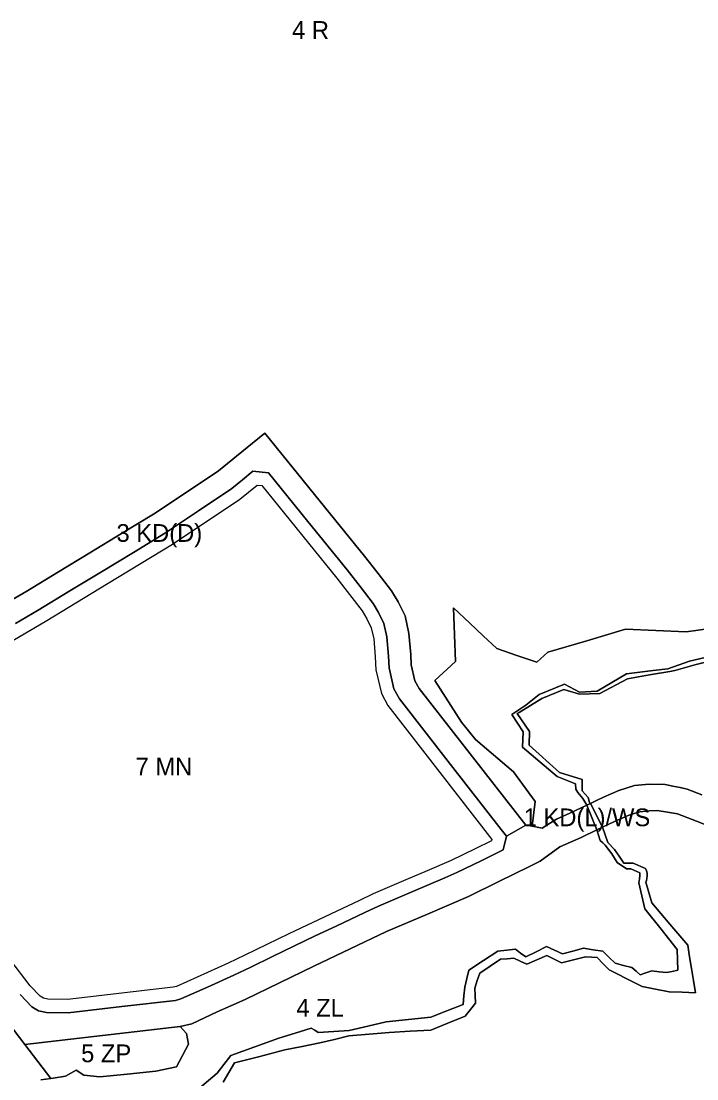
# Model space of a CAD drawing. Extents: x 7423691 to 7425475, y 5552085 to 5554331.
# Drawn here: x 7424684.6 to 7424989.2, y 5552921.5 to 5553398.6 of the extents above; entities that cross this region are included whole.
import ezdxf

# ---------------------------------------------------------------- set-up
doc = ezdxf.new("R2010")
doc.units = 0
for name, color, linetype in [('linia_zabudowy_nieprzekraczalna', 7, 'Continuous'), ('linie_rozgraniczajace', 7, 'Continuous'), ('oznaczenia_przeznaczen', 7, 'Continuous')]:
    doc.layers.add(name, color=color, linetype=linetype)

msp = doc.modelspace()

# ---------------------------------------------------------------- linework, layer by layer
at = {"layer": 'linia_zabudowy_nieprzekraczalna'}
for points in [[(7424674.46, 5553115.63), (7424695.37, 5553127.73), (7424723.87, 5553145.12), (7424752.83, 5553162.67), (7424783.11, 5553182.94), (7424790.96, 5553189.33), (7424793.03, 5553189.11), (7424826.84, 5553147.4), (7424838.36, 5553132.54), (7424840.47, 5553129.02), (7424842.45, 5553124.97), (7424843.56, 5553119.97), (7424844.25, 5553111.83), (7424844.49, 5553106.05), (7424847.02, 5553095.29), (7424849.93, 5553089.96), (7424896.85, 5553029.48)], [(7424896.85, 5553029.48), (7424896.71, 5553028.9), (7424889.27, 5553025.25), (7424878.52, 5553019.99), (7424867.66, 5553015.33), (7424858, 5553011.19), (7424843.26, 5553004.87), (7424837.06, 5553001.98), (7424823.99, 5552995.79), (7424805.25, 5552986.87), (7424785.48, 5552977.28), (7424777.98, 5552973.64), (7424754.64, 5552963.18), (7424753.04, 5552962.78), (7424705.5, 5552957.33), (7424696.62, 5552957.36), (7424694.72, 5552957.8), (7424693.22, 5552958.72), (7424688.62, 5552963.41), (7424642.68, 5553023.53)]]:
    msp.add_lwpolyline(points, dxfattribs=at)
at = {"layer": 'linie_rozgraniczajace'}
for points in [[(7424996.23, 5553124.78), (7424984.37, 5553123.2), (7424970.73, 5553123.77), (7424957.08, 5553124.35), (7424939.57, 5553119.13), (7424922.06, 5553113.91), (7424917.04, 5553109.37), (7424908.04, 5553112.51), (7424899.05, 5553115.64), (7424892.95, 5553121.31), (7424886.85, 5553126.98), (7424879.56, 5553133.99), (7424879.99, 5553121.83), (7424880.42, 5553109.68), (7424871.08, 5553101.21), (7424883.09, 5553082.35), (7424889.46, 5553074.63), (7424906.56, 5553060.01), (7424916.29, 5553046.64), (7424914.96, 5553035.43), (7424912.13, 5553035.95), (7424888.05, 5553066.79), (7424863.97, 5553097.63), (7424862.1, 5553101.06), (7424860.41, 5553108.23), (7424860.23, 5553112.84), (7424859.41, 5553122.39), (7424857.66, 5553130.28), (7424854.55, 5553136.66), (7424851.59, 5553141.58), (7424845.49, 5553149.46), (7424839.38, 5553157.34), (7424816.9, 5553185.06), (7424794.43, 5553212.79), (7424784.01, 5553204.3), (7424773.59, 5553195.81), (7424758.91, 5553185.99), (7424744.23, 5553176.17), (7424729.89, 5553167.48), (7424715.55, 5553158.79), (7424701.38, 5553150.14), (7424687.2, 5553141.48), (7424677.14, 5553135.66)], [(7424677.14, 5553135.66), (7424687.2, 5553141.48), (7424701.38, 5553150.14), (7424715.55, 5553158.79), (7424729.89, 5553167.48), (7424744.23, 5553176.17), (7424758.91, 5553185.99), (7424773.59, 5553195.81), (7424784.01, 5553204.3), (7424794.43, 5553212.79), (7424816.9, 5553185.06), (7424839.38, 5553157.34), (7424845.49, 5553149.46), (7424851.59, 5553141.58), (7424854.55, 5553136.66), (7424857.66, 5553130.28), (7424859.41, 5553122.39), (7424860.23, 5553112.84), (7424860.41, 5553108.23), (7424862.1, 5553101.06), (7424863.97, 5553097.63), (7424888.05, 5553066.79), (7424912.13, 5553035.95), (7424903.34, 5553030.91), (7424900.95, 5553033.99), (7424878.13, 5553063.34), (7424855.2, 5553092.84), (7424852.68, 5553097.46), (7424850.46, 5553106.86), (7424850.24, 5553112.21), (7424849.51, 5553120.85), (7424848.16, 5553126.96), (7424845.75, 5553131.89), (7424843.33, 5553135.93), (7424837.44, 5553143.53), (7424831.55, 5553151.12), (7424813.83, 5553172.97), (7424796.12, 5553194.82), (7424789.1, 5553195.55), (7424784.32, 5553191.66), (7424779.54, 5553187.77), (7424764.57, 5553177.75), (7424749.6, 5553167.73), (7424735.18, 5553158.99), (7424720.75, 5553150.25), (7424706.53, 5553141.57), (7424692.31, 5553132.89), (7424682, 5553126.92)], [(7424682, 5553126.92), (7424692.31, 5553132.89), (7424706.53, 5553141.57), (7424720.75, 5553150.25), (7424735.18, 5553158.99), (7424749.6, 5553167.73), (7424764.57, 5553177.75), (7424779.54, 5553187.77), (7424784.32, 5553191.66), (7424789.1, 5553195.55), (7424796.12, 5553194.82), (7424813.83, 5553172.97), (7424831.55, 5553151.12), (7424837.44, 5553143.53), (7424843.33, 5553135.93), (7424845.75, 5553131.89), (7424848.16, 5553126.96), (7424849.51, 5553120.85), (7424850.24, 5553112.21), (7424850.46, 5553106.86), (7424852.68, 5553097.46), (7424855.2, 5553092.84), (7424878.13, 5553063.34), (7424900.95, 5553033.99), (7424903.34, 5553030.91), (7424901.92, 5553024.77), (7424891.91, 5553019.86), (7424881.02, 5553014.54), (7424875.53, 5553012.18), (7424860.36, 5553005.68), (7424845.71, 5552999.39), (7424839.6, 5552996.55), (7424826.56, 5552990.37), (7424817.21, 5552985.92), (7424807.85, 5552981.46), (7424797.97, 5552976.67), (7424788.1, 5552971.89), (7424780.51, 5552968.21), (7424768.56, 5552962.85), (7424756.61, 5552957.49), (7424754.12, 5552956.86), (7424729.97, 5552954.09), (7424705.83, 5552951.32), (7424695.93, 5552951.37), (7424692.42, 5552952.17), (7424689.45, 5552954), (7424684.08, 5552959.48)], [(7424871.08, 5553101.21), (7424880.42, 5553109.68), (7424879.99, 5553121.83), (7424879.56, 5553133.99), (7424886.85, 5553126.98), (7424892.95, 5553121.31), (7424899.05, 5553115.64), (7424908.04, 5553112.51), (7424917.04, 5553109.37), (7424922.06, 5553113.91), (7424939.57, 5553119.13), (7424957.08, 5553124.35), (7424970.73, 5553123.77), (7424984.37, 5553123.2), (7424996.23, 5553124.78)], [(7424905.79, 5553085.9), (7424912.07, 5553090.07), (7424915.07, 5553092.48), (7424918.07, 5553094.9), (7424929.53, 5553099.54), (7424936.36, 5553095.91), (7424944.3, 5553096.38), (7424957.55, 5553104.18), (7424969.52, 5553105.66), (7424976.1, 5553106.47), (7424985.93, 5553109.97), (7425000.71, 5553113.41)], [(7425000.71, 5553113.41), (7424985.93, 5553109.97), (7424976.1, 5553106.47), (7424969.52, 5553105.66), (7424957.55, 5553104.18), (7424944.3, 5553096.38), (7424936.36, 5553095.91), (7424929.53, 5553099.54), (7424918.07, 5553094.9), (7424915.07, 5553092.48), (7424912.07, 5553090.07)], [(7425000.54, 5553111.18), (7424988.39, 5553108.24), (7424984.16, 5553107.01), (7424979.93, 5553105.78), (7424977.91, 5553105.34), (7424967.93, 5553103.67), (7424957.95, 5553102), (7424945.48, 5553095.32), (7424936.31, 5553095.08), (7424929.21, 5553097.1), (7424919.4, 5553093.02), (7424914.25, 5553089.91), (7424909.1, 5553086.8), (7424908.18, 5553086.25), (7424913.8, 5553078.22), (7424913.62, 5553072.01), (7424927.23, 5553059.64), (7424937.53, 5553056.58), (7424937.55, 5553051.42), (7424940.22, 5553048.35), (7424940.79, 5553046.21), (7424941.28, 5553045.73), (7424939.69, 5553044.97), (7424937.82, 5553047.93), (7424935.58, 5553050.63), (7424934.74, 5553052.11), (7424934.59, 5553054.53), (7424926.29, 5553057.86), (7424918.48, 5553064.47), (7424910.67, 5553071.08), (7424910.91, 5553077.95), (7424905.79, 5553085.9)], [(7424908.18, 5553086.25), (7424909.1, 5553086.8), (7424914.25, 5553089.91), (7424919.4, 5553093.02), (7424929.21, 5553097.1), (7424936.31, 5553095.08), (7424945.48, 5553095.32), (7424957.95, 5553102), (7424967.93, 5553103.67), (7424977.91, 5553105.34), (7424979.93, 5553105.78), (7424984.16, 5553107.01), (7424988.39, 5553108.24), (7425000.54, 5553111.18)], [(7424912.07, 5553090.07), (7424905.79, 5553085.9), (7424910.91, 5553077.95), (7424910.67, 5553071.08), (7424918.48, 5553064.47), (7424926.29, 5553057.86), (7424934.59, 5553054.53), (7424934.74, 5553052.11), (7424935.58, 5553050.63), (7424937.82, 5553047.93), (7424939.69, 5553044.97), (7424931.96, 5553041.27), (7424925.99, 5553038.57), (7424922.73, 5553036.59), (7424919.48, 5553034.61), (7424914.96, 5553035.43), (7424916.29, 5553046.64), (7424906.56, 5553060.01), (7424889.46, 5553074.63), (7424883.09, 5553082.35), (7424871.08, 5553101.21)], [(7424991.49, 5553049.58), (7424984.92, 5553052.11), (7424981.74, 5553052.9), (7424978.35, 5553053.56), (7424974.95, 5553054.21), (7424967.79, 5553054.38), (7424961.09, 5553053.79), (7424954.03, 5553051.54), (7424947.15, 5553048.54), (7424943.93, 5553047), (7424941.28, 5553045.73), (7424940.79, 5553046.21), (7424940.22, 5553048.35), (7424937.55, 5553051.42), (7424937.53, 5553056.58), (7424927.23, 5553059.64), (7424913.62, 5553072.01), (7424913.8, 5553078.22), (7424908.18, 5553086.25)], [(7424997.75, 5553034.32), (7424989.1, 5553037.64), (7424980.46, 5553040.97), (7424975.93, 5553041.71), (7424971.4, 5553042.46), (7424967.72, 5553042.44), (7424963.58, 5553041.99), (7424960.91, 5553041.14), (7424958.24, 5553040.29), (7424952.14, 5553037.63), (7424946.76, 5553035.05), (7424941.28, 5553045.73), (7424943.93, 5553047), (7424947.15, 5553048.54), (7424954.03, 5553051.54), (7424961.09, 5553053.79), (7424967.79, 5553054.38), (7424974.95, 5553054.21), (7424978.35, 5553053.56), (7424981.74, 5553052.9), (7424984.92, 5553052.11), (7424991.49, 5553049.58)], [(7424756.61, 5552957.49), (7424768.56, 5552962.85), (7424780.51, 5552968.21), (7424788.1, 5552971.89), (7424797.97, 5552976.67), (7424807.85, 5552981.46), (7424817.21, 5552985.92), (7424826.56, 5552990.37), (7424839.6, 5552996.55), (7424845.71, 5552999.39), (7424860.36, 5553005.68), (7424875.53, 5553012.18), (7424881.02, 5553014.54), (7424891.91, 5553019.86), (7424901.92, 5553024.77), (7424903.34, 5553030.91), (7424912.13, 5553035.95), (7424914.96, 5553035.43), (7424919.48, 5553034.61), (7424922.73, 5553036.59), (7424925.99, 5553038.57), (7424931.96, 5553041.27), (7424939.69, 5553044.97), (7424944.14, 5553033.8), (7424937.03, 5553030.4), (7424927.51, 5553026.08), (7424918.65, 5553019.62), (7424913.72, 5553017.19), (7424900.02, 5553010.47), (7424886.31, 5553003.75), (7424867.84, 5552995.83), (7424849.37, 5552987.9), (7424832.98, 5552980.14), (7424816.6, 5552972.37), (7424801.09, 5552964.85), (7424785.59, 5552957.33), (7424779.04, 5552954.4), (7424772.9, 5552951.64), (7424767.2, 5552948.99), (7424761.49, 5552946.35), (7424756.27, 5552945.03), (7424721.22, 5552941.01), (7424686.16, 5552936.99), (7424663.12, 5552967.14)], [(7424941.66, 5552976.34), (7424944.28, 5552976.16), (7424947.02, 5552973.41), (7424949.76, 5552970.66), (7424953.54, 5552968.72), (7424957.33, 5552966.79), (7424960.92, 5552964.97), (7424964.52, 5552963.14), (7424970.61, 5552961.93), (7424976.71, 5552960.72), (7424982.65, 5552960.52), (7424988.59, 5552960.31), (7424987.69, 5552965.77), (7424986.8, 5552971.22), (7424985.96, 5552976.46), (7424985.12, 5552981.7), (7424977, 5552991.31), (7424968.87, 5553000.93), (7424967.59, 5553005.54), (7424966.3, 5553010.16), (7424966.52, 5553011), (7424966.74, 5553011.84), (7424966.81, 5553013.06), (7424966.88, 5553014.28), (7424966.51, 5553015.29), (7424966.14, 5553016.29), (7424960.45, 5553018.81), (7424956.31, 5553018.84), (7424954.24, 5553021.91), (7424952.17, 5553024.98), (7424949.15, 5553028.03), (7424946.76, 5553035.05), (7424952.14, 5553037.63), (7424958.24, 5553040.29), (7424960.91, 5553041.14), (7424963.58, 5553041.99), (7424967.72, 5553042.44), (7424971.4, 5553042.46), (7424975.93, 5553041.71), (7424980.46, 5553040.97), (7424989.1, 5553037.64), (7424997.75, 5553034.32)], [(7424693.52, 5552920.96), (7424697.89, 5552921.64), (7424699.01, 5552921.81), (7424704.5, 5552922.66), (7424709.37, 5552925.36), (7424712.9, 5552923.14), (7424720.09, 5552922.41), (7424732.3, 5552923.62), (7424745.33, 5552924.9), (7424754.63, 5552926.84), (7424759.99, 5552937.09), (7424759.17, 5552941.94), (7424756.27, 5552945.03), (7424761.49, 5552946.35), (7424767.2, 5552948.99), (7424772.9, 5552951.64), (7424779.04, 5552954.4), (7424785.59, 5552957.33), (7424801.09, 5552964.85), (7424816.6, 5552972.37), (7424832.98, 5552980.14), (7424849.37, 5552987.9), (7424867.84, 5552995.83), (7424886.31, 5553003.75), (7424900.02, 5553010.47), (7424913.72, 5553017.19), (7424918.65, 5553019.62), (7424927.51, 5553026.08), (7424937.03, 5553030.4), (7424944.14, 5553033.8), (7424944.91, 5553031.39), (7424945.67, 5553028.99), (7424946.81, 5553027.94), (7424947.95, 5553026.89), (7424949.43, 5553024.91), (7424950.91, 5553022.92), (7424952.07, 5553020.96), (7424953.24, 5553019), (7424957.47, 5553016.15), (7424959.51, 5553016.17), (7424963.52, 5553014.42), (7424963.46, 5553013.09), (7424963.4, 5553011.76), (7424963.27, 5553010.8), (7424963.14, 5553009.85), (7424964.43, 5553003.99), (7424965.71, 5552998.13), (7424973.07, 5552988.97), (7424980.43, 5552979.82), (7424980.51, 5552975.13), (7424980.6, 5552970.44), (7424978.09, 5552969.94), (7424975.59, 5552969.43), (7424972.24, 5552969.81), (7424968.89, 5552970.18), (7424966.27, 5552969.31), (7424963.65, 5552968.44), (7424961.81, 5552970.06), (7424959.97, 5552971.67), (7424956.2, 5552972.64), (7424952.42, 5552973.61), (7424949.61, 5552976.33), (7424946.8, 5552979.05), (7424942.43, 5552979.74), (7424938.07, 5552980.42), (7424933.34, 5552979.12), (7424928.62, 5552977.82), (7424925.01, 5552979.47), (7424921.41, 5552981.13), (7424916.74, 5552978.78), (7424912.07, 5552976.44), (7424909.76, 5552978.2), (7424907.44, 5552979.95), (7424903.51, 5552979.51), (7424899.57, 5552979.07), (7424892.97, 5552974.81), (7424886.37, 5552970.56), (7424885.46, 5552966.71), (7424884.55, 5552962.86), (7424884.18, 5552958.91), (7424883.81, 5552954.97), (7424876.55, 5552952.14)], [(7424966.27, 5552969.31), (7424968.89, 5552970.18), (7424972.24, 5552969.81), (7424975.59, 5552969.43), (7424978.09, 5552969.94), (7424980.6, 5552970.44), (7424980.51, 5552975.13), (7424980.43, 5552979.82), (7424973.07, 5552988.97), (7424965.71, 5552998.13), (7424964.43, 5553003.99), (7424963.14, 5553009.85), (7424963.27, 5553010.8), (7424963.4, 5553011.76), (7424963.46, 5553013.09), (7424963.52, 5553014.42), (7424959.51, 5553016.17), (7424957.47, 5553016.15), (7424953.24, 5553019), (7424952.07, 5553020.96), (7424950.91, 5553022.92), (7424949.43, 5553024.91), (7424947.95, 5553026.89), (7424946.81, 5553027.94), (7424945.67, 5553028.99), (7424944.91, 5553031.39), (7424944.14, 5553033.8), (7424944.14, 5553033.8), (7424946.76, 5553035.05), (7424949.15, 5553028.03), (7424952.17, 5553024.98), (7424954.24, 5553021.91), (7424956.31, 5553018.84), (7424960.45, 5553018.81), (7424966.14, 5553016.29), (7424966.51, 5553015.29), (7424966.88, 5553014.28), (7424966.81, 5553013.06), (7424966.74, 5553011.84), (7424966.52, 5553011), (7424966.3, 5553010.16), (7424967.59, 5553005.54), (7424968.87, 5553000.93), (7424977, 5552991.31), (7424985.12, 5552981.7), (7424985.96, 5552976.46), (7424986.8, 5552971.22), (7424987.69, 5552965.77), (7424988.59, 5552960.31), (7424982.65, 5552960.52), (7424976.71, 5552960.72), (7424970.61, 5552961.93), (7424964.52, 5552963.14), (7424960.92, 5552964.97), (7424957.33, 5552966.79), (7424953.54, 5552968.72), (7424949.76, 5552970.66), (7424947.02, 5552973.41), (7424944.28, 5552976.16), (7424941.66, 5552976.34), (7424939.05, 5552976.52), (7424933.64, 5552975.15), (7424928.24, 5552973.78), (7424924.9, 5552975.46), (7424921.57, 5552977.14), (7424917.04, 5552975.18), (7424912.52, 5552973.23), (7424909.62, 5552974.58), (7424906.73, 5552975.93), (7424903.71, 5552975.67), (7424900.69, 5552975.42), (7424896.06, 5552972.3), (7424891.43, 5552969.17), (7424890.24, 5552965.78), (7424889.06, 5552962.38), (7424889.27, 5552959), (7424889.49, 5552955.61), (7424887.13, 5552952.69), (7424884.78, 5552949.77), (7424877.02, 5552946.61), (7424869.26, 5552943.45), (7424859.92, 5552942.92), (7424850.57, 5552942.39), (7424841.48, 5552941.61), (7424832.38, 5552940.82), (7424825.79, 5552939.27), (7424819.21, 5552937.73), (7424811.35, 5552936.12), (7424803.49, 5552934.52), (7424792.15, 5552931.57), (7424780.82, 5552928.63), (7424778.2, 5552924.32), (7424775.59, 5552920.01)], [(7424760.39, 5552913.3), (7424772.92, 5552923.98), (7424776.02, 5552928), (7424779.13, 5552932.02), (7424789.95, 5552935.93), (7424800.77, 5552939.83), (7424808.09, 5552942.12), (7424815.41, 5552944.4), (7424816.95, 5552943.36), (7424818.48, 5552942.32), (7424825.5, 5552942.79), (7424832.51, 5552943.26), (7424840.87, 5552945.19), (7424849.22, 5552947.12), (7424859.25, 5552948.21), (7424869.29, 5552949.3), (7424876.55, 5552952.14), (7424883.81, 5552954.97), (7424884.18, 5552958.91), (7424884.55, 5552962.86), (7424885.46, 5552966.71), (7424886.37, 5552970.56), (7424892.97, 5552974.81), (7424899.57, 5552979.07), (7424903.51, 5552979.51), (7424907.44, 5552979.95), (7424909.76, 5552978.2), (7424912.07, 5552976.44), (7424916.74, 5552978.78), (7424921.41, 5552981.13), (7424925.01, 5552979.47), (7424928.62, 5552977.82), (7424933.34, 5552979.12), (7424938.07, 5552980.42), (7424942.43, 5552979.74), (7424946.8, 5552979.05), (7424949.61, 5552976.33), (7424952.42, 5552973.61), (7424956.2, 5552972.64), (7424959.97, 5552971.67), (7424961.81, 5552970.06), (7424963.65, 5552968.44), (7424966.27, 5552969.31)], [(7424775.59, 5552920.01), (7424778.2, 5552924.32), (7424780.82, 5552928.63), (7424792.15, 5552931.57), (7424803.49, 5552934.52), (7424811.35, 5552936.12), (7424819.21, 5552937.73), (7424825.79, 5552939.27), (7424832.38, 5552940.82), (7424841.48, 5552941.61), (7424850.57, 5552942.39), (7424859.92, 5552942.92), (7424869.26, 5552943.45), (7424877.02, 5552946.61), (7424884.78, 5552949.77), (7424887.13, 5552952.69), (7424889.49, 5552955.61), (7424889.27, 5552959), (7424889.06, 5552962.38), (7424890.24, 5552965.78), (7424891.43, 5552969.17), (7424896.06, 5552972.3), (7424900.69, 5552975.42), (7424903.71, 5552975.67), (7424906.73, 5552975.93), (7424909.62, 5552974.58), (7424912.52, 5552973.23), (7424917.04, 5552975.18), (7424921.57, 5552977.14), (7424924.9, 5552975.46), (7424928.24, 5552973.78), (7424933.64, 5552975.15), (7424939.05, 5552976.52), (7424941.66, 5552976.34)], [(7424663.12, 5552967.14), (7424686.16, 5552936.99), (7424697.89, 5552921.64), (7424693.52, 5552920.96)], [(7424684.08, 5552959.48), (7424689.45, 5552954), (7424692.42, 5552952.17), (7424695.93, 5552951.37), (7424705.83, 5552951.32), (7424729.97, 5552954.09), (7424754.12, 5552956.86), (7424756.61, 5552957.49)], [(7424876.55, 5552952.14), (7424869.29, 5552949.3), (7424859.25, 5552948.21), (7424849.22, 5552947.12), (7424840.87, 5552945.19), (7424832.51, 5552943.26), (7424825.5, 5552942.79), (7424818.48, 5552942.32), (7424816.95, 5552943.36), (7424815.41, 5552944.4), (7424808.09, 5552942.12), (7424800.77, 5552939.83), (7424789.95, 5552935.93), (7424779.13, 5552932.02), (7424776.02, 5552928), (7424772.92, 5552923.98), (7424760.39, 5552913.3)]]:
    msp.add_lwpolyline(points, dxfattribs=at)
for points in [[(7424939.69, 5553044.97), (7424941.28, 5553045.73), (7424946.76, 5553035.05), (7424944.14, 5553033.8), (7424944.14, 5553033.8)], [(7424686.16, 5552936.99), (7424721.22, 5552941.01), (7424756.27, 5552945.03), (7424759.17, 5552941.94), (7424759.99, 5552937.09), (7424754.63, 5552926.84), (7424745.33, 5552924.9), (7424732.3, 5552923.62), (7424720.09, 5552922.41), (7424712.9, 5552923.14), (7424709.37, 5552925.36), (7424704.5, 5552922.66), (7424699.01, 5552921.81), (7424697.89, 5552921.64)]]:
    msp.add_lwpolyline(points, close=True, dxfattribs=at)

# ---------------------------------------------------------------- texts
at = {"layer": 'oznaczenia_przeznaczen'}
for s, p in [('4 R', (7424806.72, 5553390.63)), ('3 KD(D)', (7424727.58, 5553163.73)), ('7 MN', (7424736.17, 5553058.34)), ('1 KD(L)/WS', (7424911.16, 5553035.44)), ('4 ZL', (7424808.66, 5552949.55)), ('5 ZP', (7424711.61, 5552928.96))]:
    msp.add_text(s, height=8, dxfattribs=at).set_placement(p)

doc.saveas('drawing.dxf')
